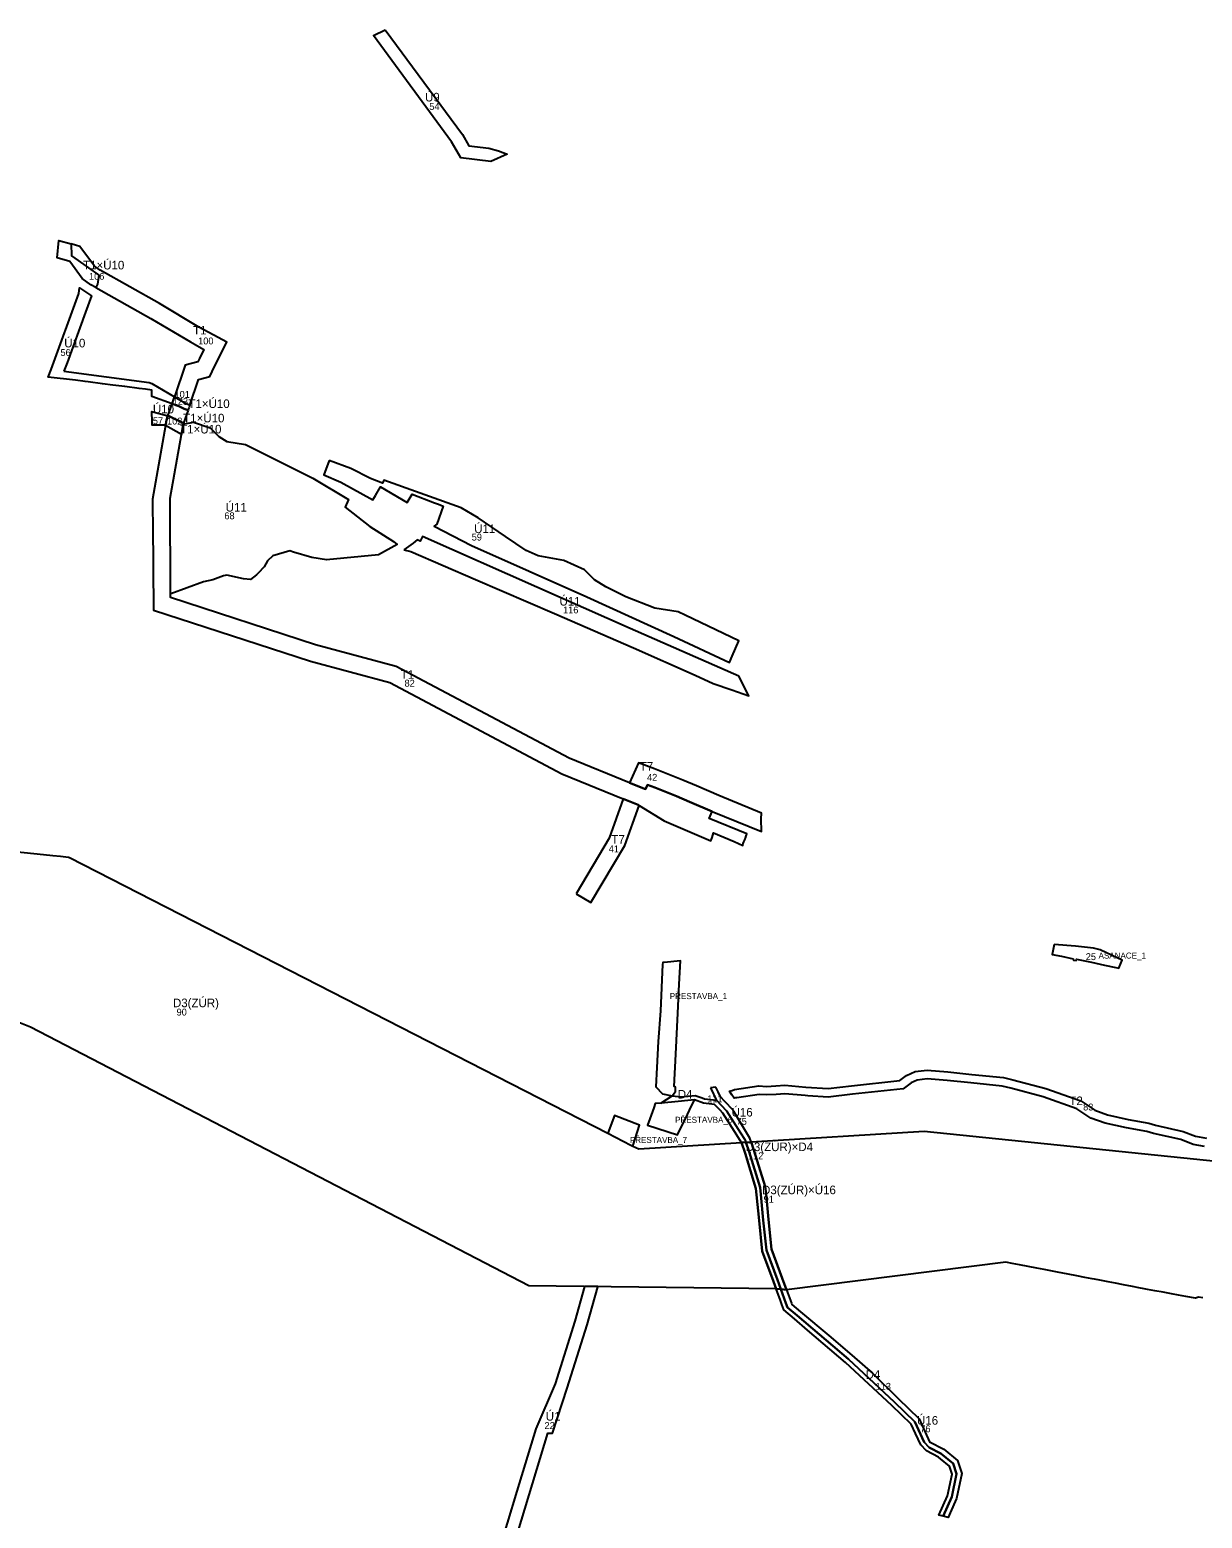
# Model space of a CAD drawing. Extents: x -521621 to -516857, y -1190025 to -1185894.
# Drawn here: x -520831 to -519468, y -1187926 to -1186195 of the extents above; entities that cross this region are included whole.
import ezdxf

# ---------------------------------------------------------------- set-up
doc = ezdxf.new("R2010")
doc.units = 0
for name, color, linetype in [('A_id', 7, 'Continuous'), ('asanace_n', 7, 'Continuous'), ('prestavba_n', 7, 'Continuous'), ('VPO_id', 7, 'Continuous'), ('VPO_n', 7, 'Continuous'), ('VPS_id', 7, 'Continuous'), ('VPS_n', 7, 'Continuous')]:
    doc.layers.add(name, color=color, linetype=linetype)

msp = doc.modelspace()

# ---------------------------------------------------------------- linework, layer by layer
at = {"layer": 'asanace_n'}
msp.add_lwpolyline([(-519640.1, -1187258.6), (-519642.2, -1187270.1), (-519631.2, -1187272.3), (-519617.7, -1187275.1), (-519617.6, -1187276.6), (-519614.5, -1187277.1), (-519613.9, -1187275.5), (-519596.5, -1187279.2), (-519581.2, -1187282.5), (-519568.1, -1187285.3), (-519564.6, -1187286), (-519560.9, -1187276.9), (-519578.9, -1187268.3), (-519586.4, -1187264.7), (-519594.2, -1187263), (-519615.3, -1187260.6), (-519640.1, -1187258.6)], dxfattribs=at)
at = {"layer": 'prestavba_n'}
for points in [[(-520084.3, -1187434.6), (-520080.4, -1187429.6), (-520080.3, -1187424.7), (-520081.9, -1187423.7), (-520079.9, -1187386), (-520077.7, -1187338.3), (-520076, -1187304.7), (-520074.5, -1187277.4), (-520093.3, -1187279.6), (-520095, -1187279.6), (-520095.3, -1187281.8), (-520097.7, -1187335.6), (-520100.3, -1187371.4), (-520101.8, -1187401.5), (-520103, -1187424.2), (-520095.2, -1187432.2), (-520084.3, -1187434.6)], [(-520097.1, -1187443.1), (-520103.8, -1187443.7), (-520105.5, -1187448.5), (-520110.1, -1187461.4), (-520112.8, -1187468.9), (-520078, -1187480), (-520066.2, -1187456.4), (-520064.1, -1187451.2), (-520058.1, -1187439.2), (-520084.9, -1187441.8), (-520097.1, -1187443.1)], [(-520132.3, -1187491.8), (-520130, -1187493), (-520122.2, -1187468.9), (-520151.1, -1187457.3), (-520159, -1187477.9), (-520132.3, -1187491.8)]]:
    msp.add_lwpolyline(points, dxfattribs=at)
at = {"layer": 'VPO_n'}
for p, q in [((-520033.3, -1187424.5), (-520039.4, -1187425.1)), ((-520033.2, -1187424.5), (-520033.3, -1187424.5))]:
    msp.add_line(p, q, dxfattribs=at)
for points in [[(-520417.7, -1186194.5), (-520328, -1186316.5), (-520320.7, -1186329.4), (-520297.3, -1186332.2), (-520286, -1186335.2), (-520275.9, -1186339.4), (-520295.1, -1186347.6), (-520330, -1186343.4), (-520340.6, -1186324.7), (-520431.4, -1186201.2)], [(-520689, -1186640.8), (-520689, -1186638.6), (-520670.4, -1186643.7), (-520672.1, -1186648.7), (-520673.2, -1186654.8), (-520673.5, -1186654.6), (-520688.9, -1186654.6), (-520688.9, -1186650.8), (-520688.9, -1186646.6), (-520689, -1186642.4)], [(-520602.1, -1186673.3), (-520580.3, -1186677), (-520501.9, -1186716.2), (-520460.6, -1186741.1), (-520464.3, -1186749.8), (-520435.6, -1186772.4), (-520408.2, -1186789.8), (-520404, -1186793.2), (-520425.4, -1186805.4), (-520486.2, -1186811.2), (-520503.1, -1186808.4), (-520524.5, -1186802), (-520528.6, -1186800.8), (-520548.3, -1186806.6), (-520554.7, -1186812.2), (-520558.4, -1186819.3), (-520565.6, -1186826.8), (-520567.5, -1186828.5), (-520570.9, -1186831.2), (-520574.5, -1186833.9), (-520582.6, -1186833.3), (-520601.9, -1186829), (-520605.8, -1186829.6), (-520618.2, -1186834.4), (-520629.1, -1186836.6), (-520667.1, -1186850.8), (-520667.4, -1186850.6), (-520667.8, -1186739.5), (-520654.8, -1186665.4), (-520652.7, -1186653.6), (-520652.2, -1186652.3), (-520650.6, -1186653.1), (-520640.9, -1186650.8), (-520621.4, -1186657.5), (-520611.2, -1186667.5)], [(-519934.8, -1187685.7), (-519901.9, -1187713.3), (-519875.1, -1187736.4), (-519851.3, -1187757), (-519821.2, -1187786.7), (-519796.9, -1187810.2), (-519784.7, -1187837), (-519768.2, -1187845.7), (-519752.4, -1187858.8), (-519747.1, -1187873.8), (-519753.4, -1187903.1), (-519760.9, -1187919.7), (-519763.2, -1187925), (-519769.1, -1187923.5), (-519759.1, -1187901.2), (-519753.3, -1187874.2), (-519757.5, -1187862.4), (-519771.6, -1187850.7), (-519785.2, -1187843.5), (-519790.9, -1187837.6), (-519801.9, -1187813.7), (-519825.4, -1187791.1), (-519879.1, -1187740.9), (-519938.7, -1187690.2), (-519950, -1187680.7), (-519951.9, -1187675.7), (-519957.8, -1187659.5), (-519951.1, -1187660.2), (-519945.5, -1187675.7), (-519944.9, -1187677.2)]]:
    msp.add_lwpolyline(points, close=True, dxfattribs=at)
for points in [[(-520806.4, -1186589.8), (-520774.1, -1186501.4), (-520773.1, -1186494.9), (-520759.2, -1186504.2), (-520766.1, -1186523.1), (-520787.7, -1186581.9), (-520791.3, -1186591.7)], [(-520696.5, -1186612.7), (-520703.8, -1186611.8), (-520720.7, -1186609.6), (-520734.4, -1186607.8), (-520746.6, -1186606.3), (-520763, -1186604.1), (-520766.8, -1186603.7), (-520777.9, -1186602.3), (-520809.6, -1186598.6), (-520806.4, -1186589.8)], [(-520791.3, -1186591.7), (-520692.2, -1186605), (-520689.3, -1186606)], [(-520689.3, -1186606), (-520662.9, -1186621.4), (-520663.4, -1186623.1), (-520664, -1186624.7), (-520664.7, -1186626.7), (-520665.7, -1186629.7), (-520689.1, -1186621.2), (-520689.1, -1186619.3), (-520689.2, -1186617.4), (-520689.2, -1186615.5), (-520689.2, -1186613.7), (-520696.5, -1186612.7)], [(-520483, -1186695.4), (-520489.2, -1186712.1), (-520469.5, -1186720.7), (-520432, -1186741.4), (-520429, -1186736.3), (-520423.1, -1186726.3), (-520392.1, -1186744.3), (-520386.3, -1186734.9), (-520360.4, -1186744.7), (-520355.9, -1186746.4), (-520350.4, -1186748.5), (-520357.9, -1186769.5), (-520360.9, -1186771.9), (-520317.4, -1186794.6), (-520183.2, -1186854.2), (-520082.3, -1186900.2), (-520017.5, -1186930.4), (-520014.4, -1186923.2), (-520006.7, -1186905.2), (-520068.8, -1186875.6), (-520077.1, -1186871.6), (-520104.1, -1186867.2), (-520138.1, -1186854.2), (-520161.4, -1186842.7), (-520174.4, -1186834.4), (-520185.9, -1186822.9), (-520210.1, -1186811.7), (-520240.1, -1186806.4), (-520253.9, -1186800.1), (-520278.1, -1186783.8), (-520309.6, -1186762.1), (-520329.5, -1186750.8), (-520419.4, -1186718.5), (-520421, -1186721.8), (-520434.7, -1186716.6), (-520457.7, -1186705), (-520483, -1186695.4)], [(-520396.3, -1186799.3), (-520387.8, -1186801.4), (-520312.7, -1186834), (-520221, -1186873.7), (-520129.2, -1186913.4), (-520057.4, -1186945.2), (-520036.3, -1186954.9), (-520014.6, -1186962.4), (-519994.8, -1186969.5), (-520006.4, -1186946.6), (-520132.9, -1186890.9), (-520241.6, -1186842.9), (-520374.5, -1186784), (-520377.1, -1186789.5), (-520380.6, -1186787.9), (-520385.2, -1186791.6), (-520396.3, -1186799.3)], [(-520039.4, -1187425.1), (-520038.8, -1187426.7)], [(-520038.8, -1187426.7), (-520032.9, -1187439.3)], [(-520033, -1187425.1), (-520033.2, -1187424.5)], [(-520033, -1187425.1), (-520033, -1187425.1)], [(-520030.7, -1187430), (-520033, -1187425.1)], [(-520032.9, -1187439.3), (-520027.3, -1187445.3)], [(-520027.9, -1187435.9), (-520030.7, -1187430)], [(-520022.9, -1187441.2), (-520027.9, -1187435.9)], [(-520013.3, -1187451.3), (-520022.9, -1187441.2)], [(-520027.3, -1187445.3), (-520020.8, -1187452.1)], [(-520020.8, -1187452.1), (-520004.7, -1187477.6), (-519999.7, -1187485.5)], [(-520012.3, -1187453), (-520013.3, -1187451.3)], [(-519999.7, -1187485.5), (-519999.2, -1187486.2), (-519998.5, -1187488.4), (-519995.4, -1187488.3), (-519992.3, -1187488.1), (-519993.8, -1187483.7), (-520012.3, -1187453)], [(-520273.1, -1187974.4), (-520250.5, -1187898.7), (-520228.5, -1187827.1), (-520223.4, -1187827.1), (-520206.2, -1187774.7), (-520182.9, -1187701.1), (-520170.6, -1187656.6), (-520170.6, -1187656.5), (-520186.1, -1187656.3), (-520197.3, -1187696.8), (-520220.3, -1187769.5), (-520242.6, -1187822), (-520264.9, -1187894.4), (-520287.1, -1187968.9)]]:
    msp.add_lwpolyline(points, dxfattribs=at)
at = {"layer": 'VPS_n'}
for points in [[(-520770, -1186483.8), (-520784.7, -1186463.9), (-520799.1, -1186459.9), (-520797.2, -1186439.6), (-520783, -1186443.6)], [(-520783, -1186443.6), (-520782.5, -1186457.5)], [(-520610.9, -1186575.9), (-520608.8, -1186571.6), (-520601.9, -1186558), (-520611.9, -1186552.6), (-520634.4, -1186540.3), (-520680.3, -1186513), (-520749.2, -1186474.3), (-520755.7, -1186469.5), (-520772.7, -1186446.5), (-520783, -1186443.6), (-520782.5, -1186457.5), (-520774.7, -1186463.1), (-520750.6, -1186480.1), (-520752.2, -1186490.3), (-520754.3, -1186494.4), (-520690.3, -1186530.3), (-520644.3, -1186557.7), (-520638.9, -1186560.6), (-520628.5, -1186566.3), (-520633.9, -1186577.1), (-520635.7, -1186580.7), (-520650.4, -1186584.7), (-520662.9, -1186621.4), (-520655.4, -1186625.8), (-520652.7, -1186627.4), (-520649.5, -1186629.2), (-520647.3, -1186630.2), (-520645.1, -1186631.2), (-520634.9, -1186601.2), (-520621.9, -1186597.7), (-520616.1, -1186586.1), (-520610.9, -1186575.9)], [(-520782.5, -1186457.5), (-520774.7, -1186463.1), (-520750.6, -1186480.1), (-520752.2, -1186490.3), (-520754.3, -1186494.4), (-520760.1, -1186491.2), (-520770, -1186483.8)], [(-520670.4, -1186643.7), (-520665.7, -1186629.7)], [(-520665.7, -1186629.7), (-520657.7, -1186632.5)], [(-520652.2, -1186652.3), (-520669.1, -1186644.1), (-520670.4, -1186643.7)], [(-520657.7, -1186632.5), (-520654.8, -1186633.8)], [(-520654.8, -1186633.8), (-520651.4, -1186635.3)], [(-520647.1, -1186637.2), (-520652.2, -1186652.3)], [(-520651.4, -1186635.3), (-520647.1, -1186637.2)], [(-520001.4, -1187141.2), (-520000.6, -1187139), (-519999.8, -1187136.8), (-519998.6, -1187133.9), (-519998.5, -1187133.4), (-519997.5, -1187130.9), (-519997.3, -1187130.5), (-519997.2, -1187130), (-520041.1, -1187111.9), (-520037.7, -1187103.7), (-520063.8, -1187092.5), (-520079.2, -1187086), (-520104.1, -1187076.1), (-520112.7, -1187072.8), (-520115, -1187077.9), (-520133.6, -1187070.6), (-520203.8, -1187041.8), (-520405, -1186935.1), (-520498.9, -1186909.9), (-520667.4, -1186855), (-520667.4, -1186850.6), (-520667.8, -1186739.5), (-520654.8, -1186665.4), (-520673.2, -1186654.8), (-520688.2, -1186740.5), (-520688, -1186781.6), (-520687.8, -1186807), (-520687.6, -1186824.5), (-520687.6, -1186830.6), (-520687.6, -1186835.5), (-520687.4, -1186853.1), (-520687.3, -1186869.5), (-520504.6, -1186929.1), (-520412.3, -1186953.8), (-520212.4, -1187059.9), (-520140.9, -1187089.3), (-520123.5, -1187096.1), (-520122.4, -1187096.8), (-520093.3, -1187114.7), (-520039.2, -1187137.8), (-520037.7, -1187134.1), (-520036.1, -1187128.8), (-520011.9, -1187138.8), (-520001.8, -1187143.5), (-520001.4, -1187141.2)], [(-520115, -1187077.9), (-520112.7, -1187072.8), (-520104.1, -1187076.1), (-520079.2, -1187086), (-520063.8, -1187092.5), (-520037.7, -1187103.7), (-519980.3, -1187127.3), (-519980.7, -1187112.2), (-519980.3, -1187105.7), (-520030, -1187085.2), (-520056, -1187074.1), (-520071.6, -1187067.5), (-520096.8, -1187057.5), (-520104.8, -1187054.4), (-520123.4, -1187047.1), (-520133.6, -1187070.6), (-520115, -1187077.9)], [(-520195.7, -1187199.5), (-520178.5, -1187209.7), (-520139.1, -1187143.4), (-520122.4, -1187096.8), (-520123.5, -1187096.1), (-520140.9, -1187089.3), (-520157.3, -1187134.8), (-520195.7, -1187199.5)], [(-520849, -1187150.2), (-520815.2, -1187153.9), (-520804.3, -1187155.1), (-520795.3, -1187156), (-520786.2, -1187157), (-520784.9, -1187157.2), (-520159, -1187477.9), (-520132.3, -1187491.8), (-520130, -1187493), (-520122.9, -1187496.1), (-520003.6, -1187488.8), (-519999.4, -1187501.1), (-519986.8, -1187542.4), (-519985.9, -1187549.9), (-519983.1, -1187579.6), (-519979.3, -1187615.3), (-519966.4, -1187650.5), (-519963.3, -1187659), (-520250.8, -1187655.6), (-520830.3, -1187354.9), (-520886.9, -1187332.1)], [(-519465, -1187493.7), (-519478.4, -1187491.1), (-519492.8, -1187485.5), (-519524.5, -1187478.3), (-519532.1, -1187476.1), (-519555.7, -1187471.8), (-519580.6, -1187466.2), (-519597.1, -1187460.4), (-519613.5, -1187449.6), (-519652.6, -1187435.8), (-519690.3, -1187425.6), (-519700.4, -1187423.3), (-519736.7, -1187419.6), (-519764.5, -1187416.6), (-519787.4, -1187414.9), (-519799.1, -1187416.2), (-519806.3, -1187419.4), (-519815.4, -1187426.6), (-519874.4, -1187432.7), (-519902.6, -1187436.1), (-519926.4, -1187434.5), (-519929.4, -1187434.3), (-519953.1, -1187432.2), (-519963, -1187432.9), (-519974.6, -1187433.6), (-519982.9, -1187432.9), (-520009.1, -1187436.9), (-520010.5, -1187437.1), (-520012, -1187437.3), (-520014.8, -1187433.3), (-520017.5, -1187429.2), (-520014.5, -1187428.2), (-520011.5, -1187427.1), (-519983.2, -1187422.8), (-519974.4, -1187423.6), (-519963.6, -1187423), (-519953, -1187422.2), (-519928.6, -1187424.4), (-519902.8, -1187426), (-519875.5, -1187422.8), (-519819.3, -1187416.9), (-519811.5, -1187410.8), (-519801.7, -1187406.4), (-519787.5, -1187404.9), (-519763.6, -1187406.6), (-519735.7, -1187409.7), (-519698.8, -1187413.4), (-519687.9, -1187415.9), (-519649.6, -1187426.2), (-519609, -1187440.6), (-519592.6, -1187451.4), (-519577.8, -1187456.6), (-519553.7, -1187462), (-519529.8, -1187466.3), (-519522, -1187468.6), (-519489.9, -1187475.9), (-519475.7, -1187481.4), (-519462.8, -1187483.9)], [(-520028.4, -1187451.3), (-520034.9, -1187444.5), (-520047.6, -1187443), (-520058.1, -1187439.2), (-520084.9, -1187441.8), (-520097.1, -1187443.1), (-520084.3, -1187434.6), (-520073.6, -1187435.7), (-520057.4, -1187434.1), (-520049.2, -1187437.1), (-520046.4, -1187438.1), (-520032.5, -1187439.7), (-520027.3, -1187445.3), (-520020.8, -1187452.1)], [(-520003.6, -1187488.8), (-520003.8, -1187488.4), (-520008.9, -1187480.3), (-520025, -1187454.8), (-520028.4, -1187451.3)], [(-520020.8, -1187452.1), (-520004.7, -1187477.6), (-519999.7, -1187485.5), (-519999.2, -1187486.2), (-519998.5, -1187488.4), (-520003.6, -1187488.8)], [(-519467.2, -1187669.7), (-519472.1, -1187668.6), (-519475.5, -1187670.1), (-519486.8, -1187668), (-519495.4, -1187666.4), (-519503.6, -1187664.9), (-519513.2, -1187663.1), (-519522.7, -1187661.3), (-519531.3, -1187659.7), (-519535.2, -1187659), (-519541.3, -1187657.8), (-519548.9, -1187656.4), (-519559.1, -1187654.4), (-519568.5, -1187652.6), (-519577.2, -1187651), (-519587, -1187649.1), (-519592.9, -1187647.9), (-519595.9, -1187647.4), (-519604.1, -1187645.8), (-519613.4, -1187644), (-519623.8, -1187642), (-519636, -1187639.7), (-519642, -1187638.6), (-519651.6, -1187636.7), (-519660.2, -1187635.1), (-519670.3, -1187633.1), (-519680.2, -1187631.2), (-519688.7, -1187629.6), (-519696.3, -1187628.1), (-519951.1, -1187660.2), (-519956.1, -1187646.7), (-519968.5, -1187612.8), (-519972.2, -1187578.6), (-519974.9, -1187548.7), (-519976, -1187540.1), (-519989, -1187497.8), (-519992.3, -1187488.1), (-519790.9, -1187475.7), (-519421.5, -1187513.5)], [(-520003.6, -1187488.8), (-519998.5, -1187488.4)], [(-519998.5, -1187488.4), (-519994.7, -1187499.6), (-519981.9, -1187541.3), (-519980.9, -1187549.3), (-519978.1, -1187579.2), (-519974.4, -1187614.2), (-519961.7, -1187648.8), (-519957.8, -1187659.5), (-519963.3, -1187659), (-519966.4, -1187650.5), (-519979.3, -1187615.3), (-519983.1, -1187579.6), (-519985.9, -1187549.9), (-519986.8, -1187542.4), (-519999.4, -1187501.1), (-520003.6, -1187488.8)]]:
    msp.add_lwpolyline(points, dxfattribs=at)
for points in [[(-520665.7, -1186629.7), (-520662.9, -1186621.4), (-520655.4, -1186625.8), (-520652.7, -1186627.4), (-520649.5, -1186629.2), (-520647.3, -1186630.2), (-520645.1, -1186631.2), (-520645.5, -1186632.5), (-520645.9, -1186633.8), (-520646.5, -1186635.5), (-520647.1, -1186637.2), (-520651.4, -1186635.3), (-520654.8, -1186633.8), (-520657.7, -1186632.5)], [(-520670.4, -1186643.7), (-520669.1, -1186644.1), (-520652.2, -1186652.3), (-520652.7, -1186653.6), (-520654.8, -1186665.4), (-520673.2, -1186654.8), (-520672.1, -1186648.7)], [(-519992.3, -1187488.1), (-519989, -1187497.8), (-519976, -1187540.1), (-519974.9, -1187548.7), (-519972.2, -1187578.6), (-519968.5, -1187612.8), (-519956.1, -1187646.7), (-519951.1, -1187660.2), (-519957.8, -1187659.5), (-519961.7, -1187648.8), (-519974.4, -1187614.2), (-519978.1, -1187579.2), (-519980.9, -1187549.3), (-519981.9, -1187541.3), (-519994.7, -1187499.6), (-519998.5, -1187488.4)], [(-519957.8, -1187659.5), (-519951.9, -1187675.7), (-519950, -1187680.7), (-519938.7, -1187690.2), (-519879.1, -1187740.9), (-519825.4, -1187791.1), (-519801.9, -1187813.7), (-519790.9, -1187837.6), (-519785.2, -1187843.5), (-519771.6, -1187850.7), (-519757.5, -1187862.4), (-519753.3, -1187874.2), (-519759.1, -1187901.2), (-519769.1, -1187923.5), (-519774, -1187922.2), (-519763.9, -1187899.7), (-519758.5, -1187874.5), (-519761.7, -1187865.3), (-519772, -1187856.8), (-519774.4, -1187854.9), (-519788.2, -1187847.5), (-519795.1, -1187840.5), (-519801.2, -1187827.2), (-519806.1, -1187816.7), (-519828.8, -1187794.7), (-519882.4, -1187744.6), (-519926.7, -1187707), (-519941.9, -1187694.1), (-519954.2, -1187683.7), (-519956.5, -1187677.4), (-519958.3, -1187672.7), (-519963.3, -1187659)]]:
    msp.add_lwpolyline(points, close=True, dxfattribs=at)

# ---------------------------------------------------------------- texts
at = {"layer": 'A_id'}
msp.add_text('25', height=8, dxfattribs=at).set_placement((-519603.2, -1187276.7))
at = {"layer": 'asanace_n'}
msp.add_text('ASANACE_1', height=7, dxfattribs=at).set_placement((-519588.3, -1187274.9))
at = {"layer": 'prestavba_n'}
for s, p in [('PŘESTAVBA_1', (-520086.9, -1187322.1)), ('PŘESTAVBA_6', (-520080.7, -1187466)), ('PŘESTAVBA_7', (-520133.3, -1187489.4))]:
    msp.add_text(s, height=7, dxfattribs=at).set_placement(p)
at = {"layer": 'VPO_id'}
for s, p in [('54', (-520366.5, -1186287.8)), ('56', (-520795.4, -1186574)), ('57', (-520688, -1186653.3)), ('68', (-520604.8, -1186763.9)), ('59', (-520317.2, -1186788.7)), ('116', (-520211, -1186873.4)), ('75', (-520009.2, -1187468.3)), ('22', (-520232.5, -1187822.1)), ('76', (-519795.6, -1187825.9))]:
    msp.add_text(s, height=8, dxfattribs=at).set_placement(p)
at = {"layer": 'VPO_n'}
for s, p in [('Ú9', (-520371.5, -1186277.9)), ('Ú10', (-520791, -1186564)), ('Ú10', (-520687.9, -1186640.7)), ('Ú11', (-520603.3, -1186755)), ('Ú11', (-520314.3, -1186780)), ('Ú11', (-520215.1, -1186864.3)), ('Ú16', (-520015, -1187458.7)), ('Ú1', (-520231.1, -1187812.4)), ('Ú16', (-519799.4, -1187817.1))]:
    msp.add_text(s, height=10, dxfattribs=at).set_placement(p)
at = {"layer": 'VPS_id'}
for s, p in [('106', (-520762.2, -1186485.3)), ('100', (-520635.3, -1186560.5)), ('123', (-520664.9, -1186630.8)), ('101', (-520662.8, -1186622.7)), ('102', (-520671.5, -1186653.7)), ('82', (-520395.3, -1186958.6)), ('42', (-520113.3, -1187068.1)), ('41', (-520157.9, -1187151.4)), ('90', (-520660.4, -1187341.2)), ('111', (-520043.3, -1187442.1)), ('83', (-519606.2, -1187451.6)), ('112', (-519996, -1187508.4)), ('91', (-519977.8, -1187558.9)), ('113', (-519847.6, -1187776.5))]:
    msp.add_text(s, height=8, dxfattribs=at).set_placement(p)
at = {"layer": 'VPS_n'}
for s, p in [('T1×Ú10', (-520769.1, -1186473.3)), ('T1', (-520641.1, -1186549)), ('T1×Ú10', (-520646.6, -1186634.5)), ('T1×Ú10', (-520652.7, -1186651.2)), ('T1×Ú10', (-520656.2, -1186664.1)), ('T1', (-520399.8, -1186949.5)), ('T7', (-520121.8, -1187056.4)), ('T7', (-520154.8, -1187141.3)), ('D3(ZÚR)', (-520664.6, -1187331.5)), ('D4', (-520077.6, -1187437.7)), ('T2', (-519622.2, -1187445.4)), ('D3(ZÚR)×D4', (-519998.7, -1187498.9)), ('D3(ZÚR)×Ú16', (-519979.6, -1187549)), ('D4', (-519859.2, -1187763.8))]:
    msp.add_text(s, height=10, dxfattribs=at).set_placement(p)

doc.saveas('drawing.dxf')
